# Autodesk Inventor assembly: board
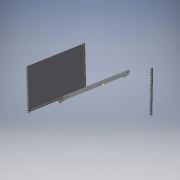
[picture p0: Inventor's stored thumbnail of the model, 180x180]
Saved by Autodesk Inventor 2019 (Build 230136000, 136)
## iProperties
Created: 2019-11
Part Number: board
Document SubType Name: Assembly
Designer: PRADYUMNA
Author: PRADYUMNA
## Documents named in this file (8)
- C:\Users\Sangeetha Jathar\Desktop\New folder\bhanu\board.iam
- C:\Users\Sangeetha Jathar\Desktop\New folder\bhanu\boardf.ipt
- C:\Users\Sangeetha Jathar\Desktop\New folder\bhanu\rack.ipt
- C:\Users\Sangeetha Jathar\Desktop\New folder\bhanu\gear.ipt
- C:\Users\Sangeetha Jathar\Desktop\New folder\bhanu\Lchannel.ipt
- C:\Users\Sangeetha Jathar\Desktop\New folder\bhanu\motor.ipt
- C:\Users\Sangeetha Jathar\Desktop\New folder\bhanu\jvsuv.ipt
- C:\Users\Sangeetha Jathar\Desktop\New folder\cchannel.ipt
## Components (13 placed, 7 different names)
1. boardf:2 — Mate:1, Mate:14, Mate:15, Mate:16, Mate:20, Mate:21, Mate:22, Mate:23, Mate:24, Mate:25, Mate:26
2. rack:2 — Mate:1, Mate:16, Mate:27, Mate:28, Mate:29
3. gear:1 — Mate:13
4. gear:2 — Mate:9, Mate:10
5. Lchannel:1 — Mate:3, Mate:4, Mate:5, Mate:6, Mate:14, Mate:15
6. motor:1 — Mate:3, Mate:4, Mate:7, Mate:8
7. motor:2 — Mate:5, Mate:6, Mate:11, Mate:12
8. jvsuv:1 — Mate:7, Mate:8, Mate:9, Mate:10
9. jvsuv:2 — Mate:11, Mate:12, Mate:13
10. cchannel:1 — Mate:20, Mate:21, Mate:22, Mate:27, Mate:28, Mate:29
11. cchannel:2 — Mate:23, Mate:24, Mate:25, Mate:26
12. rack:3
13. rack:4
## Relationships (25: Mate 25)
- Mate:1: boardf:2 ↔ rack:2
- Mate:3: Lchannel:1 ↔ motor:1
- Mate:4: Lchannel:1 ↔ motor:1
- Mate:5: Lchannel:1 ↔ motor:2
- Mate:6: Lchannel:1 ↔ motor:2
- Mate:7: motor:1 ↔ jvsuv:1
- Mate:8: motor:1 ↔ jvsuv:1
- Mate:9: gear:2 ↔ jvsuv:1
- Mate:10: gear:2 ↔ jvsuv:1
- Mate:11: motor:2 ↔ jvsuv:2
- Mate:12: motor:2 ↔ jvsuv:2
- Mate:13: gear:1 ↔ jvsuv:2
- Mate:14: boardf:2 ↔ Lchannel:1
- Mate:15: boardf:2 ↔ Lchannel:1
- Mate:16: boardf:2 ↔ rack:2
- Mate:20: boardf:2 ↔ cchannel:1
- Mate:21: boardf:2 ↔ cchannel:1
- Mate:22: boardf:2 ↔ cchannel:1
- Mate:23: boardf:2 ↔ cchannel:2
- Mate:24: boardf:2 ↔ cchannel:2
- Mate:25: boardf:2 ↔ cchannel:2
- Mate:26: boardf:2 ↔ cchannel:2
- Mate:27: rack:2 ↔ cchannel:1
- Mate:28: rack:2 ↔ cchannel:1
- Mate:29: rack:2 ↔ cchannel:1
